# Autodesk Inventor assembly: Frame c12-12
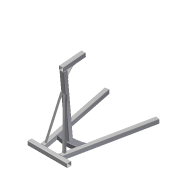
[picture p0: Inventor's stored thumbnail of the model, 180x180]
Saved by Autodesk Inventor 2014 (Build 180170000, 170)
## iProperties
Created: 2011-01
Part Number: Frame c12-12
Document SubType Name: Assembly
Designer: Thom Tremblay
_FrameDoc: Frame Assembly
_Version: 15.0.0
Author: Thom Tremblay
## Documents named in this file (20)
- C:\Inventor 2014 Essentials\Assemblies\Chapter 12\Frame\Frame c12-11.iam
- C:\Inventor 2014 Essentials\Assemblies\Chapter 12\Frame\Skeleton-c12-11.ipt
- C:\Inventor 2014 Essentials\Assemblies\Chapter 12\Frame\ANSI L 1.5 x 1.5 x 3_16 00000090.ipt
- ANSI L 1.5 x 1.5 x 3_16 00000005.ipt
- C:\Inventor 2014 Essentials\Assemblies\Chapter 12\Frame\ANSI L 1.5 x 1.5 x 3_16 00000091.ipt
- ANSI L 1.5 x 1.5 x 3_16 00000006.ipt
- C:\Inventor 2014 Essentials\Assemblies\Chapter 12\Frame\ANSI 2 1_4x5_16 00000090.ipt
- ANSI 2 1_4x5_16 00000007.ipt
- C:\Inventor 2014 Essentials\Assemblies\Chapter 12\Frame\ANSI 3x3x3_16 00000090.ipt
- ANSI 3x3x3_16 00000049.ipt
- C:\Inventor 2014 Essentials\Assemblies\Chapter 12\Frame\ANSI 3x3x3_16 00000091.ipt
- ANSI 3x3x3_16 00000050.ipt
- C:\Inventor 2014 Essentials\Assemblies\Chapter 12\Frame\ANSI 3x3x3_16 00000092.ipt
- ANSI 3x3x3_16 00000051.ipt
- C:\Inventor 2014 Essentials\Assemblies\Chapter 12\Frame\ANSI 3x3x3_16 00000093.ipt
- ANSI 3x3x3_16 00000052.ipt
- C:\Inventor 2014 Essentials\Assemblies\Chapter 12\Frame\ANSI 3x3x3_16 00000094.ipt
- ANSI 3x3x3_16 00000054.ipt
- C:\Inventor 2014 Essentials\Assemblies\Chapter 12\Frame\ANSI 5x3x3_16 00000095.ipt
- ANSI 5x3x3_16 00000057.ipt
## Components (10 placed, 10 different names)
1. Frame Reference Model
2. ANSI L 1.5 x 1.5 x 3_16 00000005:1
3. ANSI L 1.5 x 1.5 x 3_16 00000006:1
4. ANSI 2 1_4x5_16 00000007:1
5. ANSI 3x3x3_16 00000049:1
6. ANSI 3x3x3_16 00000050:1
7. ANSI 3x3x3_16 00000051:1
8. ANSI 3x3x3_16 00000052:1
9. ANSI 3x3x3_16 00000054:1
10. ANSI 5x3x3_16 00000057:1
